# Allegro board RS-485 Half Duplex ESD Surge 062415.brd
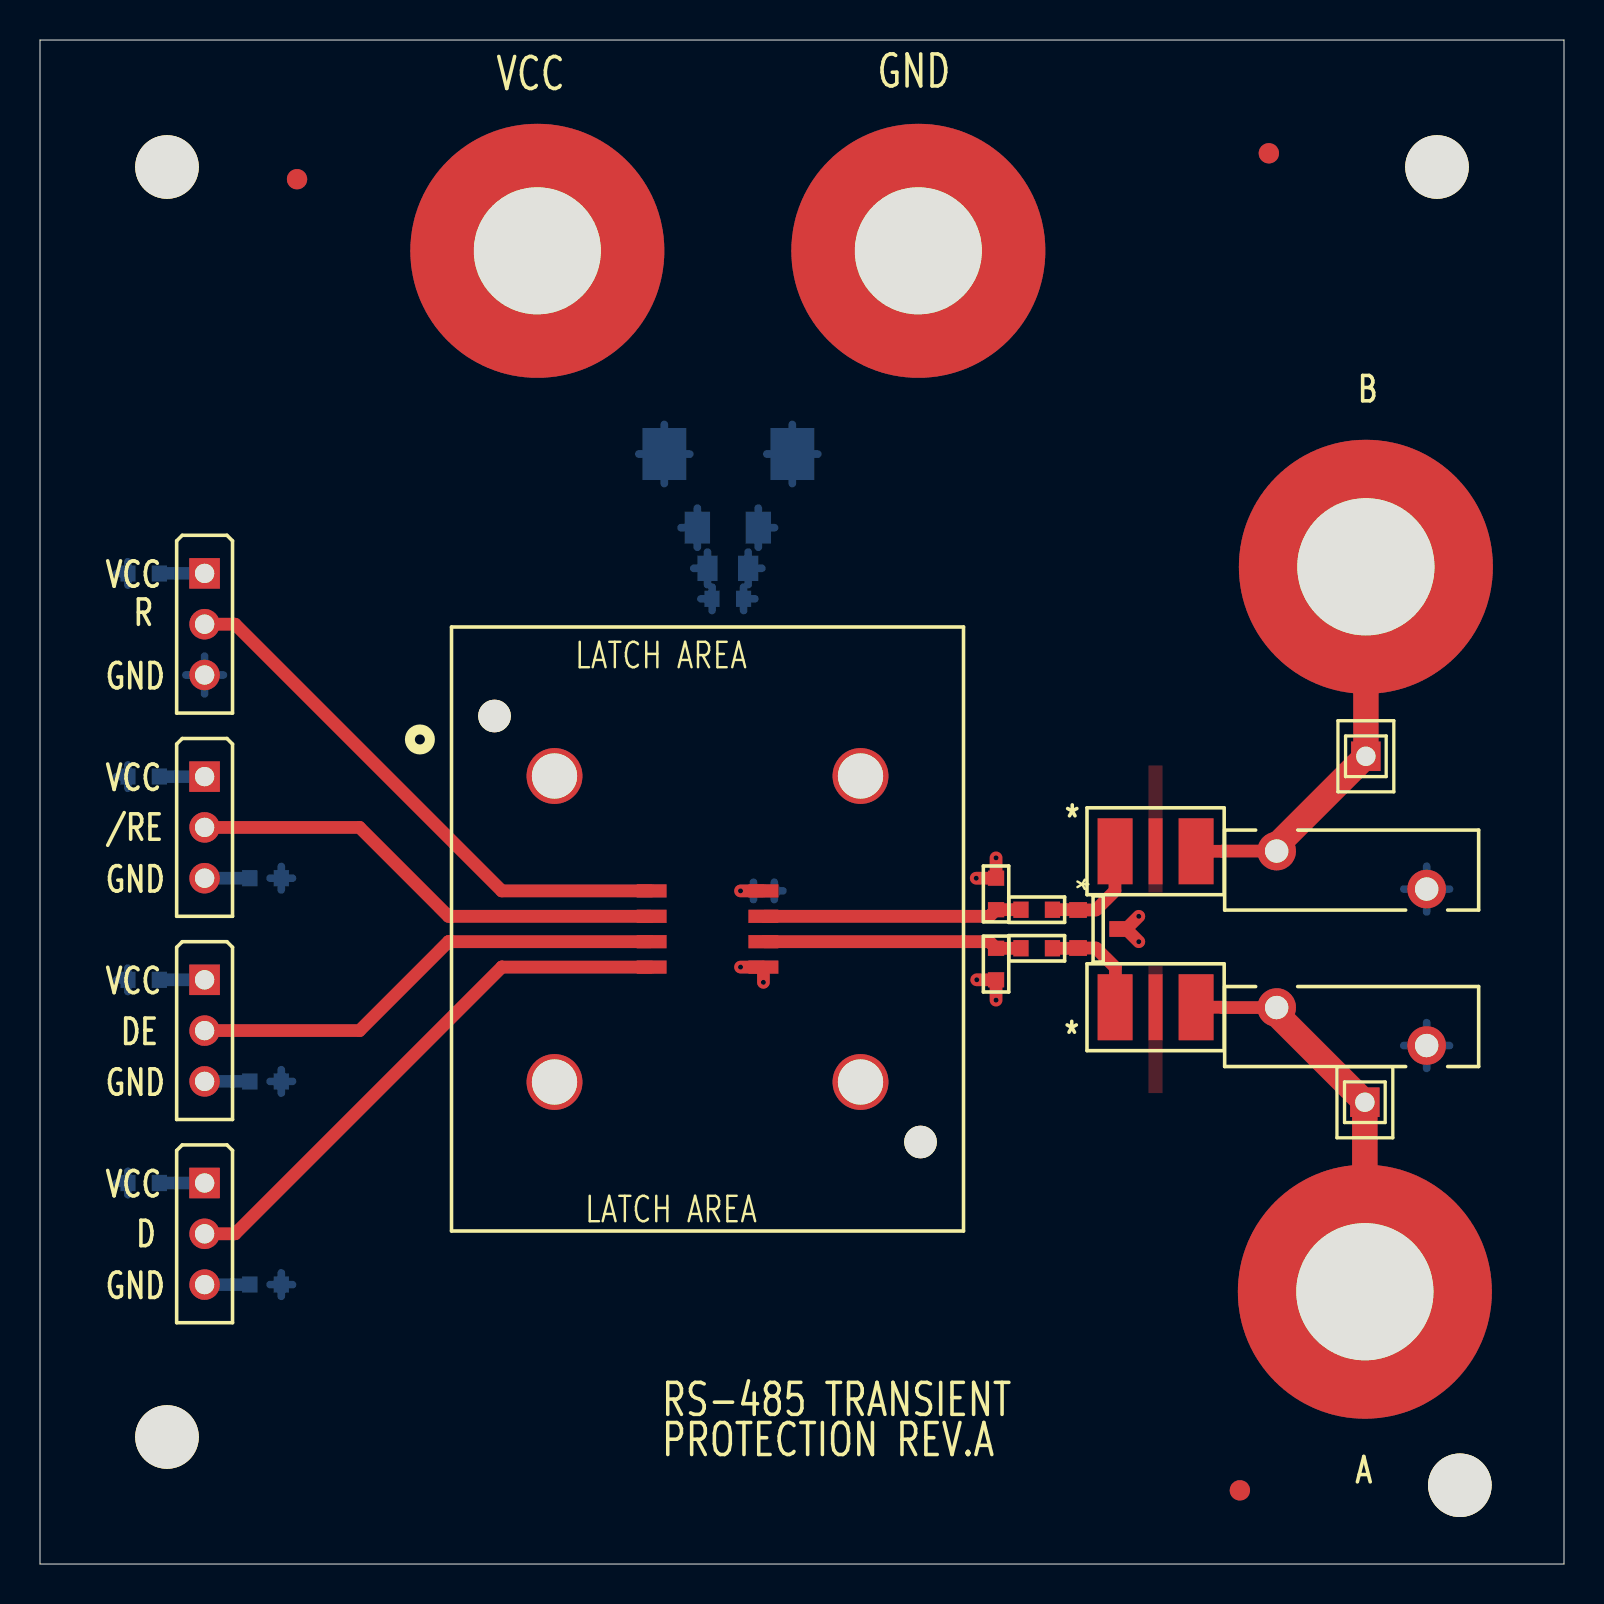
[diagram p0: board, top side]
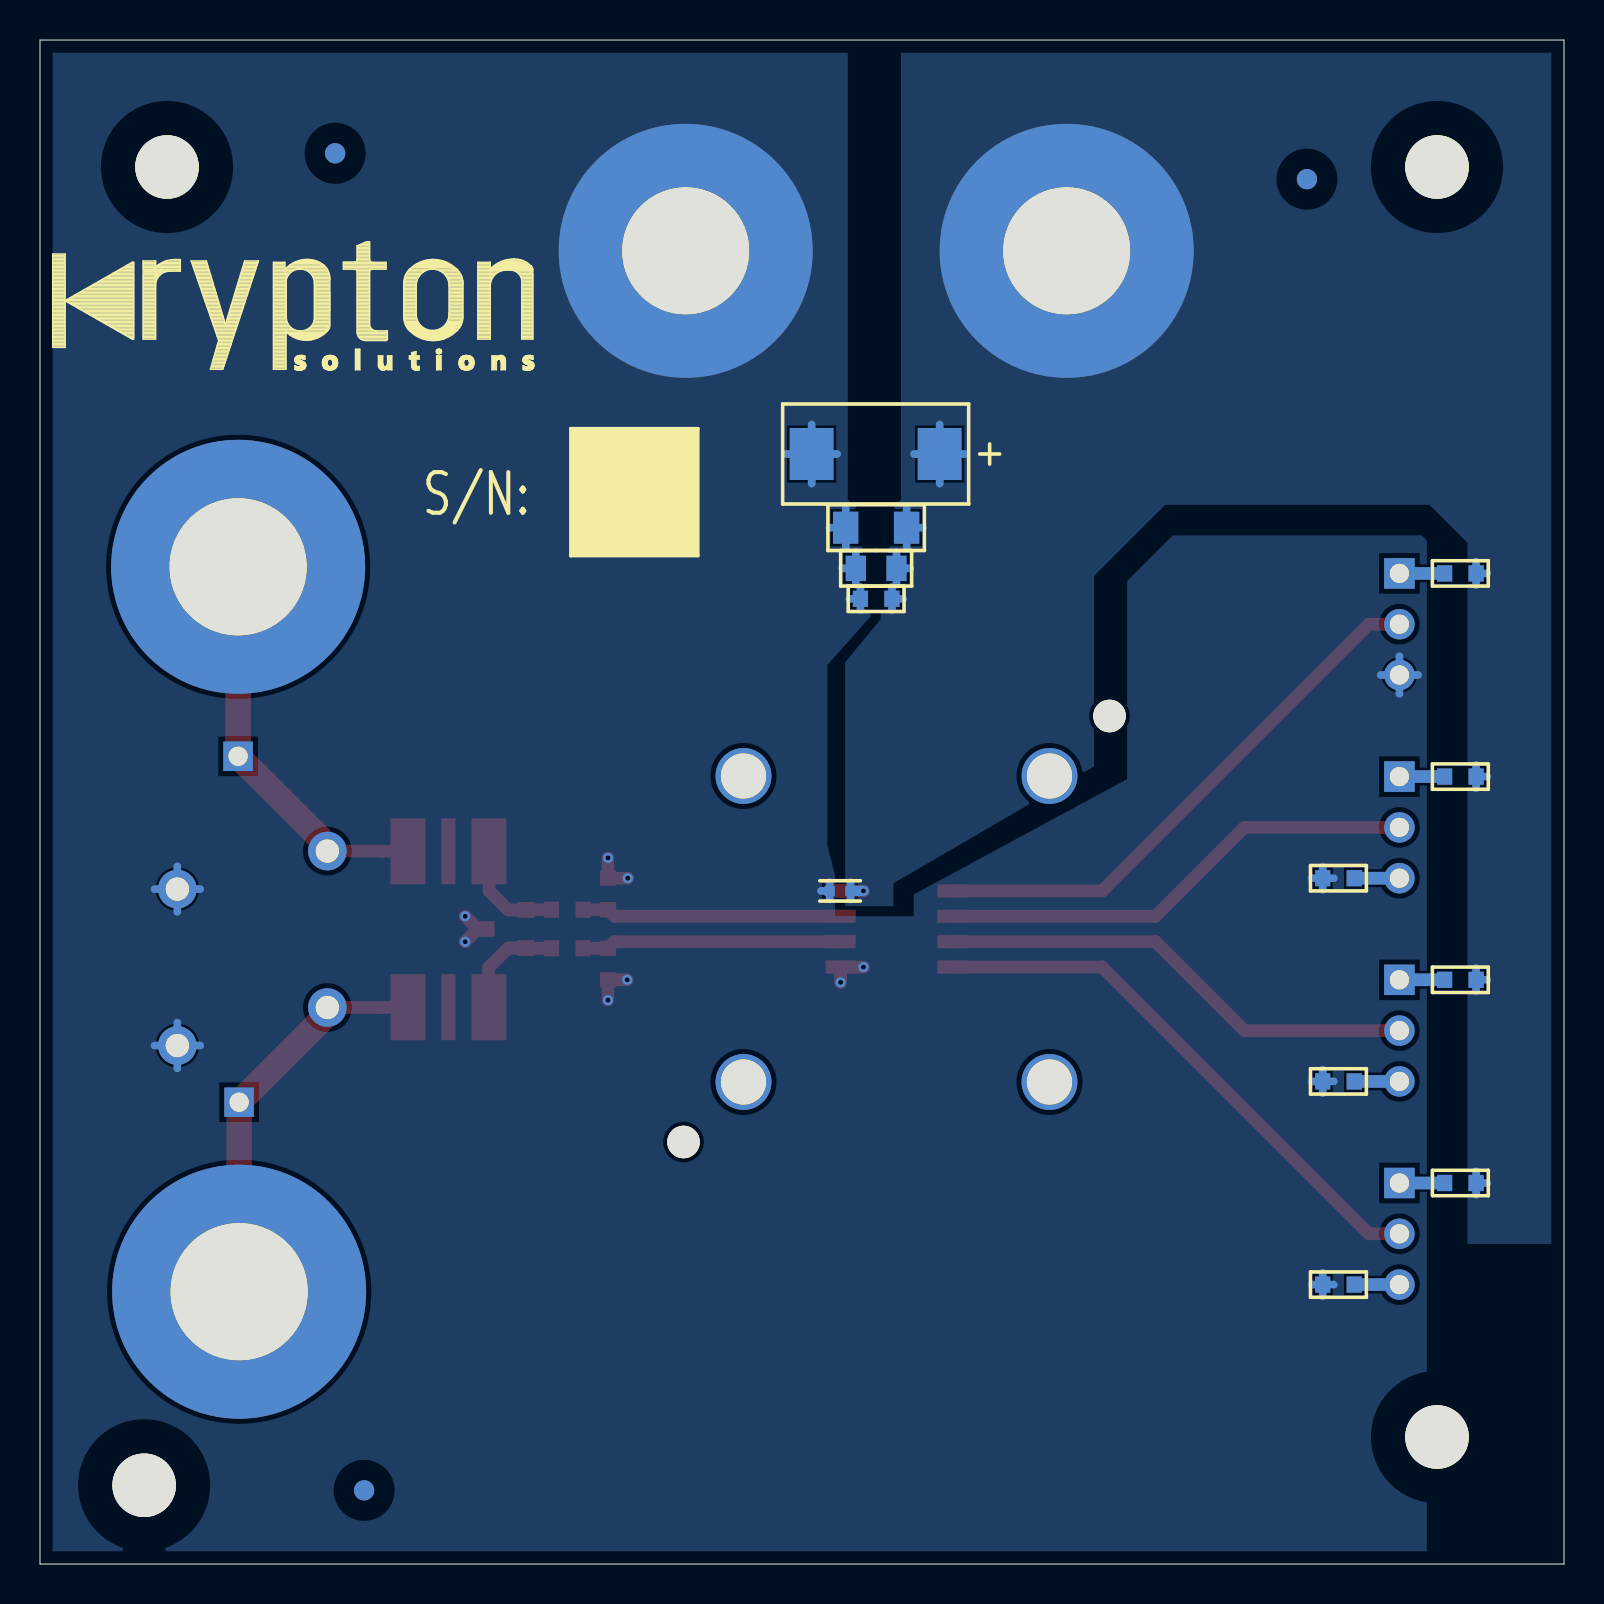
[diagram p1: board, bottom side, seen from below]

Outline 76.2 x 76.2 mm; copper layers: TOP, BOTTOM. Coordinates in mm from the lower left corner of the outline.
Outline path: 0,76.2 76.2,76.2 76.2,0 0,0 0,76.2

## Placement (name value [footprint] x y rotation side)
C1  10uf  [7343]  31.22 55.5 0 bottom
C2  2.2uF  [1206]  34.39 51.82 0 bottom
C3  1uF  [0805]  34.39 49.78 0 bottom
C4  0.1uF  [0603]  34.39 48.26 0 bottom
C5  0.1uF  [0402]  36.2 33.66 0 bottom
C6  DNI  [0603]  47.8 33.5 270 top
C7  DNI  [0603]  47.8 30 270 top
D1  TVS  [SOT_23_321]  52.91 31.75 270 top
J1  RED  [BANANA_JACK_270MIL]  66.29 49.86 0 top
J2  RED  [BANANA_JACK_270MIL]  66.24 13.61 0 top
JMP1  Header 3x1  [BERG1X3]  8.23 49.53 0 top
JMP2  Header 3x1  [BERG1X3]  8.23 39.37 0 top
JMP3  Header 3x1  [BERG1X3]  8.23 29.21 0 top
JMP4  Header 3x1  [BERG1X3]  8.23 19.05 0 top
JMP5  HMTSW-101-07-G-S-.240  [HDR_THVT_1X1]  66.29 40.39 0 top
JMP6  HMTSW-101-07-G-S-.240  [HDR_THVT_1X1]  66.24 23.09 0 top
MOV1  MOV-10D201K  [VAR_DISC_3P8X12P5MM]  65.58 34.7 0 top
MOV2  MOV-10D201K  [VAR_DISC_3P8X12P5MM]  65.58 26.87 0 top
NOREF  -  [unnamed]  6.35 6.35 0 top
NOREF#2  -  [unnamed]  70.99 3.94 0 top
NOREF#3  -  [unnamed]  59.99 3.68 0 top
NOREF#4  -  [#2]  0 0 0 top
NOREF#5  -  [unnamed]  61.44 70.54 0 top
NOREF#6  -  [#2]  88.9 38.1 0 top
NOREF#7  -  [unnamed]  12.85 69.24 0 top
NOREF#8  -  [#2]  0 76.2 0 top
NOREF#9  -  [#2]  10.24 1.42 0 top
NOREF#10  -  [unnamed]  69.85 69.85 0 top
NOREF#11  -  [#2]  76.2 0 90 top
NOREF#12  -  [#2]  -3.81 -69.85 0 top
NOREF#13  -  [unnamed]  6.35 69.85 0 top
NOREF#14  -  [#2]  75.62 59.66 180 bottom
NOREF#15  -  [#2]  56.64 53.59 180 bottom
NOREF#16  -  [unnamed]  61.44 70.54 180 bottom
NOREF#17  -  [#2]  8.64 59.69 180 bottom
NOREF#18  -  [unnamed]  59.99 3.68 180 bottom
NOREF#19  -  [unnamed]  12.85 69.24 180 bottom
P1  Banana-Jack  [BJACK]  24.87 65.66 0 top
P2  Banana-Jack  [BJACK]  43.92 65.66 0 top
R1  DNI  [0603]  5.18 49.53 0 bottom
R2  49.9  [0603]  5.18 39.37 0 bottom
R3  49.9  [0603]  11.28 34.29 0 bottom
R4  49.9  [0603]  5.18 29.21 0 bottom
R5  49.9  [0603]  11.28 24.13 0 bottom
R6  49.9  [0603]  5.18 19.05 0 bottom
R7  49.9  [0603]  11.28 13.97 0 bottom
R8  10  [0603]  49.83 32.72 0 top
R9  10  [0603]  49.83 30.78 0 top
TBU1  TBU-CA065-200-WH  [DFN_3_157X256]  55.78 35.64 0 top
TBU2  TBU-CA065-200-WH  [DFN_3_157X256]  55.78 27.84 0 top
U1  8D Half-Duplex  [SKT_SK02-0008SOP-QS-05A]  33.38 31.75 0 top

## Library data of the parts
C1 = PCap7343_10uf: tolerance: +/- 10%
C2 = NPCap1206_1.0uf: tolerance: +/- 10%
C3 = NPCap1206_0.1uf: tolerance: +/- 10%
C4 C5 = NPCap0805_0.01uf: tolerance: +/- 10%
C6 C7 = CAP_0603
D1 = Dual Bi-Directional TVS Diode
J1 J2 = BANANA_JACK_RED_RoHS
JMP1-JMP4 = Header 3x1
JMP5 JMP6 = HEADER_1x1
MOV1 MOV2 = MOV-10D201K
P1 P2 = Banana-Jack: User Part Number: 3267
R1-R9 = r0603
TBU1 TBU2 = TBU-CA-065-200-WH_2
U1 = 8 PIN DEVICE

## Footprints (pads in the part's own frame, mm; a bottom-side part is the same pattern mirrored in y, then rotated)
0402
  rect 0.508x0.508 smd: 1(-0.521,0) 2(0.521,0)
0603
  rect 0.762x0.813 smd: 1(-0.787,0) 2(0.787,0)
0805
  rect 1.016x1.27 smd: 1(-1.016,0) 2(1.016,0)
1206
  rect 1.27x1.6 smd: 1(-1.524,0) 2(1.524,0)
7343
  rect 2.2x2.601 smd: 1(0,0) 2(6.4,0)
BANANA_JACK_270MIL
  round 12.7 hole 6.858: 1(0,0)
BERG1X3
  rect 1.524x1.524 hole 0.965: 1(0,0)
  round 1.524 hole 0.965: 2(0,-2.54) 3(0,-5.08)
BJACK
  round 12.7 hole 6.35: 1(0,0)
DFN_3_157X256
  rect 1.75x3.3 smd: 1(-2.025,0) 3(2.025,0)
  rect 0.7x3.3 smd: 2(0,0)
HDR_THVT_1X1
  rect 1.473x1.473 hole 0.965: 1(0,0)
SKT_SK02-0008SOP-QS-05A
  round 1.626 hole 1.626 unplated: (-10.65,10.65) (10.65,-10.65)
  round 2.794 hole 2.261: (-7.65,7.65) (-7.65,-7.65) (7.65,7.65) (7.65,-7.65)
  rect 1.5x0.66 smd: 1(-2.795,1.905) 2(-2.795,0.635) 3(-2.795,-0.635) 4(-2.795,-1.905) 5(2.795,-1.905) 6(2.795,-0.635) 7(2.795,0.635) 8(2.795,1.905)
SOT_23_321
  rect 0.787x0.889 smd: 1(-0.953,-1.003) 2(0.953,-1.003) 3(0,1.003)
unnamed
  round 3.175 hole 3.175 unplated: (0,0)
VAR_DISC_3P8X12P5MM
  round 1.93 hole 1.168: 1(-3.75,0.95) 2(3.75,-0.95)

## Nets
GND1: C1.2 C2.2 C3.2 C4.2 C5.2 C6.1 C7.2 D1.3 JMP1.3 MOV1.2(OUT) MOV2.2(OUT) P2.1(V) R3.2 R5.2 R7.2 U1.5
VCC: C1.1 C2.1 C3.1 C4.1 C5.1 P1.1(V) R1.1 R2.1 R4.1 R6.1 U1.8
/RE: JMP2.2 U1.2
DE: JMP3.2 U1.3
HS1: TBU1.2(LINE_OUT)
HS2: TBU2.2(LINE_OUT)
R: JMP1.2 U1.1
N01583: JMP4.2 U1.4
N524936: JMP2.1 R2.2
N525001: JMP2.3 R3.1
N525305: JMP3.1 R4.2
N525367: JMP3.3 R5.1
N525470: JMP4.1 R6.2
N525494: JMP4.3 R7.1
N525767: JMP1.1 R1.2
N527204: D1.2 R9.2 TBU2.1(LINE_IN)
N527213: D1.1 R8.2 TBU1.1(LINE_IN)
N527222: C6.2 R8.1 U1.7
N527234: C7.1 R9.1 U1.6
N4743981: J1.1 JMP5.1 MOV1.1(IN) TBU1.3(NC)
N4743985: J2.1 JMP6.1 MOV2.1(IN) TBU2.3(NC)

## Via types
v1: diameter 0.508, hole 0.254, TOP to BOTTOM, 9 vias

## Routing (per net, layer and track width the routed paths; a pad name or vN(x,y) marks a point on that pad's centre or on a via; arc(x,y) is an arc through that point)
GND1: length 41.5
  TOP w0.635: v1(35.03,29.84) U1.5 v1(36.17,29.08) ; 54.31,31.75 v1(54.94,31.11) ; 54.31,31.75 v1(54.94,32.38) ; 54.31,31.75 D1.3 ; v1(46.84,29.21) C7.2 v1(47.8,28.19) ; v1(46.81,34.29) C6.1 v1(47.8,35.31)
  BOTTOM w0.381: JMP1.3 9.17,44.45 ; JMP1.3 8.23,43.51 ; JMP1.3 8.23,45.39 ; JMP1.3 7.29,44.45 ; 69.33,32.6 MOV1.2 ; MOV1.2 69.33,34.89 ; MOV1.2 70.48,33.75 ; MOV1.2 68.19,33.75 ; MOV2.2 70.48,25.92 ; MOV2.2 69.33,24.78 ; MOV2.2 69.33,27.07 ; MOV2.2 68.19,25.92 ; R7.2 12.06,14.55 ; R7.2 12.62,13.97 ; R7.2 12.06,13.39 ; R7.2 11.51,13.97 ; 36.34,55.5 C1.2 ; C1.2 37.62,54.02 ; C1.2 37.62,56.98 ; C1.2 38.89,55.5 ; 35.41,48.97 C3.2 ; C3.2 36.09,49.78 ; C3.2 35.41,50.6 ; R3.2 12.06,34.87 ; R3.2 12.62,34.29 ; R3.2 12.06,33.71 ; R3.2 11.51,34.29 ; R5.2 12.62,24.13 ; R5.2 11.51,24.13 ; R5.2 12.06,24.71 ; R5.2 12.06,23.55 ; 35.18,47.68 35.18,48.26 ; 35.18,48.26 35.18,48.84 ; 35.18,48.26 35.74,48.26 ; C5.2 37.15,33.66 ; C5.2 36.72,33.22 ; C5.2 36.72,34.09 ; 35.92,50.84 C2.2 ; C2.2 35.92,52.79 ; C2.2 36.73,51.82
VCC: length 21.9
  TOP w0.635: U1.8 v1(35.03,33.66)
  BOTTOM w0.381: 31.22,54.02 C1.1 ; C1.1 31.22,56.98 ; C1.1 32.49,55.5 ; C1.1 29.94,55.5 ; 3.83,29.21 R4.1 ; R4.1 4.39,29.79 ; R4.1 4.39,28.63 ; 35.67,33.22 C5.1 35.67,34.09 ; 3.83,19.05 R6.1 ; R6.1 4.39,18.47 ; R6.1 4.39,19.63 ; C3.1 33.38,50.6 ; C3.1 33.38,48.97 ; C3.1 32.69,49.78 ; 32.87,50.84 C2.1 ; C2.1 32.05,51.82 ; C2.1 32.87,52.79 ; 4.39,38.79 R2.1 ; R2.1 3.83,39.37 ; R2.1 4.39,39.95 ; 4.39,48.95 R1.1 ; R1.1 3.83,49.53 ; R1.1 4.39,50.11 ; C4.1 33.6,48.84 ; C4.1 33.04,48.26 ; C4.1 33.6,47.68
  BOTTOM w0.508: v1(35.03,33.66) C5.1
/RE: length 24.2
  TOP w0.635: U1.2 20.42,32.38 15.98,36.83 JMP2.2
DE: length 24.2
  TOP w0.635: U1.3 20.43,31.11 20.43,31.12 15.98,26.67 JMP3.2
R: length 27.9
  TOP w0.635: U1.1 23.09,33.66 9.75,46.99 JMP1.2
N01583: length 27.9
  TOP w0.635: U1.4 23.1,29.84 23.09,29.85 9.75,16.51 JMP4.2
N524936: length 2.3
  BOTTOM w0.635: JMP2.1 R2.2
N525001: length 2.3
  BOTTOM w0.635: JMP2.3 R3.1
N525305: length 2.3
  BOTTOM w0.635: JMP3.1 R4.2
N525367: length 2.3
  BOTTOM w0.635: JMP3.3 R5.1
N525470: length 2.3
  BOTTOM w0.635: JMP4.1 R6.2
N525494: length 2.3
  BOTTOM w0.635: JMP4.3 R7.1
N525767: length 2.3
  BOTTOM w0.635: JMP1.1 R1.2
N527204: length 5.5
  TOP w0.635: R9.2 51.89,30.78 D1.2 52.79,30.8 53.77,29.82 53.77,27.86 TBU2.1
N527213: length 5.5
  TOP w0.635: TBU1.1 53.75,35.63 53.75,33.66 52.79,32.7 D1.1 51.89,32.72 R8.2
N527222: length 13
  TOP w0.635: U1.7 47.47,32.38 C6.2 R8.1
N527234: length 13
  TOP w0.635: U1.6 47.47,31.11 C7.1 R9.1
N4743981: length 20.1
  TOP w0.635: TBU1.3 59.12,35.64 59.13,35.65 MOV1.1 61.83,35.92
  TOP w1.27: J1.1 JMP5.1 61.83,35.92
N4743985: length 20.1
  TOP w0.635: TBU2.3 59.12,27.84 59.14,27.82 MOV2.1 61.83,27.5
  TOP w1.27: J2.1 JMP6.1 61.83,27.5

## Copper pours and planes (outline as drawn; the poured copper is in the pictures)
GND1 on BOTTOM: 63.31,0.64 6.86,0.64 6.86,51.18 7.11,51.44 19.56,51.44 21.84,49.15 21.84,39.24 32.51,33.48 32.51,32.38 36.45,32.38 36.45,34.42 36.83,35.94 36.83,44.96 34.67,47.37 34.67,48.64 34.8,49.02 34.8,50.42 35.18,50.93 35.18,52.7 35.81,53.21 35.81,75.56 75.56,75.56 75.56,0.64 63.32,0.64
VCC on BOTTOM: 0.64,16 0.64,75.56 33.15,75.56 33.15,53.21 33.66,52.7 33.66,50.93 34.04,50.42 34.04,49.02 34.16,48.64 34.16,47.24 35.94,45.09 35.94,32.89 33.53,32.89 33.53,34.04 23.5,39.88 23.5,49.4 19.94,52.96 6.73,52.96 4.83,51.05 4.83,16
HS1 on TOP: 55.42,33.58 55.42,39.93 56.13,39.93 56.13,33.58
HS2 on TOP: 55.42,29.9 55.42,23.55 56.13,23.55 56.13,29.9

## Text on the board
BOTTOM: LAYER 4 - BOTTOM SIDE
Board Geometry/Soldermask Bottom: SOLDERMASK BOTTOM
Package Geometry/Pastemask Bottom: PASTEMASK BOTTOM
Ref Des/Silkscreen Bottom: SILKSCREEN BOTTOM
TOP: LAYER 1 - TOP SIDE
Board Geometry/Soldermask Top: SOLDERMASK TOP
Package Geometry/Pastemask Top: PASTEMASK TOP
Ref Des/Silkscreen Top: VCC | GND | /RE | DE | R | D | A | B | SILKSCREEN TOP | RS-485 TRANSIENT | PROTECTION REV.A
XSECTION_CHART: * AIR 0 MIL | * SOLDERMASK-0.8MIL 0.8 MIL | L1: COPPER_1/2OZ_PLATED 1.4 MIL | * CORE_1.50 57.6 MIL | L2: COPPER_1/2OZ_PLATED 1.4 MIL | DESIGN CROSS SECTION CHART | ___________________________ | TOTAL THICKNESS 62 MIL | 1-2
DIMENSION: FABRICATION DRAWING | CAD ORIGIN
PAGE_OUTLINE: LAYER 1 | LAYER 2 | LAYER 3 | LAYER 4 | LAYER | NO. | TABLE 1: | TOP | L2_GND | L3_PWR | BOTTOM | NAME | DIFFIRENTIAL PAIR | IMPEDANCE (OHMS) | DIFF TRACE | WIDTH | SPACING | SINGLE ENDED | TRACE WIDTH | REFERENCE | SPECIAL FAB NOTES: | PLACE DRILL CHART HERE: | 1:FAB SHOP MUST FOLLOW THE SOLDER MASK REVIEW LAYERS. | 2: | MIN. ANNULAR RING 2 MIL EXTERNAL PER IPC-6012C CLASS 2 | REGISTRATION TOLERANCES: METAL +/- X MIL,HOLES +/- X MIL | IMPEDANCE CONTROL: | BOARD SIZE (REFER ALSO ARRAY/PANEL PROFILING INFORMATION) | MIXED DIELECTRIC: | LAMINATE MATERIAL: | THICKNESS: | TOLERANCE: | COPPER THICKNESS (FINISHED): | BOARD FINISH: | NUMBER OF LAYERS: | MIN. TRACK WIDTH: | MIN. CLEARANCE  : | MIN. VIA PAD/DRILL: | THIEVING ALLOWED: | X | OUTER: | INNER SIGNAL: | INNER PLANE: | OTHER: | SILKSCREEN: | SOLDERMASK: (PER IPC-6011,6012) | BOARD SURFACE TREATMENT: | ADDITIONAL REQUIREMENTS: | VENDOR MARKING: | SILKSCREEN COLOR: | SOLDERMASK COLOR: | THROUGH-HOLE VIA TREATMENT: | VIA FILL USING NON-CONDUCTIVE EPOXY: | FOR WIRE BONDING: | VENDOR DATE CODE,UL,LOGO: | FR-4 HIGH Tg | 0.062" +/-10% | IPC-6012C TYPE 3 CLASS 2 | OTHER +/- | MICRO-SECTION | CERTIFICATES OF COMPLIANCE | NICKEL/GOLD (ENIG) | IMMERSION TIN | HARD GOLD | IN AN OPEN AREA | 1/4 OZ. | OPEN | NO | 2 | 25.0 MIL | X.X MIL | 20/10 MIL | NONE | DESIGN INFORMATION | ROGERS 4350B | 0.093" +/-10% | YES | TDR REPORTS/COUPONS | WHITE | GREEN | SOFT GOLD | TENTED | 1/2 OZ. | BOW & TWIST: | ORGANIC (OSP) | OTHER | WHERE INDICATED (SEE DRAWING) | YES - SEE TABLE 1 | ETCH | IDENTIFIER: | BLUE | RoHS | 1.0 OZ. | SILKSCREEN | PER SUPPLIED ARTWORK | ALL x MIL VIAS | ELECTRICAL TEST | UL 94V-0 | HASL | 2.0 OZ. | BREAK-AWAY | ENEPIG
User.10: FIGURE | SIZE | 10.0 | 38.0 | 46.0 | 89.0 | 250.0 | 270.0 | 64.0 | 125.0 | DRILL CHART: TOP to BOTTOM | ALL UNITS ARE IN MILS | TOLERANCE | +3.0/-10.0 | +3.0/-3.0 | +2.0/-2.0 | PLATED | NON-PLATED | QTY | 9 | 12 | 2 | 4
